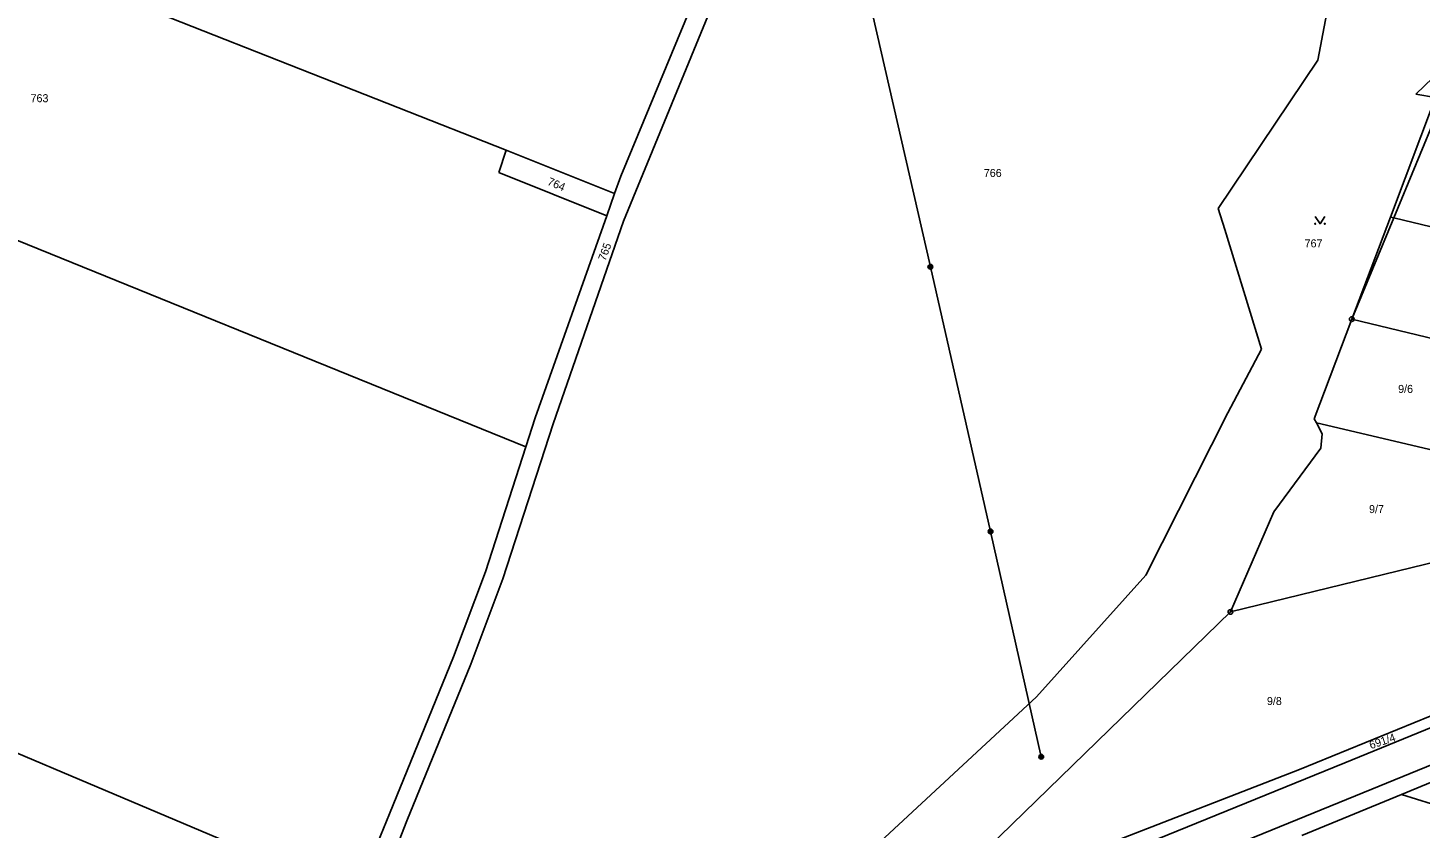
# Model space of a CAD drawing. Extents: x -738131 to -734179, y -1033447 to -1030078.
# Drawn here: x -736626.5 to -736330.8, y -1032337 to -1032166.9 of the extents above; entities that cross this region are included whole.
import ezdxf

# ---------------------------------------------------------------- set-up
doc = ezdxf.new("R2010")
doc.units = 0
for name, color, linetype in [('Vrstva 1', 7, 'Continuous'), ('Vrstva 2', 7, 'Continuous'), ('Vrstva 3', 7, 'Continuous'), ('Vrstva 4', 7, 'Continuous'), ('Vrstva 6', 7, 'Continuous'), ('Vrstva 8', 7, 'Continuous')]:
    doc.layers.add(name, color=color, linetype=linetype)

msp = doc.modelspace()

# ---------------------------------------------------------------- linework, layer by layer
at = {"layer": 'Vrstva 1'}
for points in [[(-736500.59, -1032198.46), (-736474.94, -1032136.53)], [(-736471.25, -1032138.06), (-736500.01, -1032208)], [(-736524.9, -1032192.93), (-736640.1, -1032147.52)], [(-736349.56, -1032158.09), (-736352.54, -1032173.8)], [(-736352.54, -1032173.8), (-736373.67, -1032205.35)], [(-736331.67, -1032181.03), (-736324.54, -1032174.18)], [(-736337.12, -1032207.13), (-736327.53, -1032181.71)], [(-736327.53, -1032181.71), (-736331.67, -1032181.03)], [(-736524.9, -1032192.93), (-736526.51, -1032197.67)], [(-736524.9, -1032192.93), (-736501.9, -1032202.15)], [(-736526.51, -1032197.67), (-736503.58, -1032206.9)], [(-736501.9, -1032202.15), (-736500.59, -1032198.46)], [(-736503.58, -1032206.9), (-736501.9, -1032202.15)], [(-736647.76, -1032204.41), (-736520.74, -1032255.93)], [(-736373.67, -1032205.35), (-736372.27, -1032209.79)], [(-736518.76, -1032249.79), (-736503.58, -1032206.9)], [(-736500.01, -1032208), (-736514.97, -1032251.07)], [(-736345.31, -1032228.83), (-736337.12, -1032207.13)], [(-736336.37, -1032207.29), (-736337.12, -1032207.13)], [(-736296.74, -1032216.86), (-736336.37, -1032207.29)], [(-736372.27, -1032209.79), (-736364.51, -1032235.17)], [(-736353.3, -1032250.02), (-736345.31, -1032228.83)], [(-736345.31, -1032228.83), (-736305.65, -1032238.38)], [(-736364.51, -1032235.17), (-736371.65, -1032248.71)], [(-736520.74, -1032255.93), (-736518.76, -1032249.79)], [(-736371.65, -1032248.71), (-736389.06, -1032283.24)], [(-736525.62, -1032284.03), (-736514.97, -1032251.07)], [(-736352.83, -1032250.89), (-736353.3, -1032250.02)], [(-736314.55, -1032259.88), (-736352.83, -1032250.89)], [(-736351.58, -1032253.21), (-736352.83, -1032250.89)], [(-736351.91, -1032256.24), (-736351.58, -1032253.21)], [(-736529.33, -1032282.53), (-736520.74, -1032255.93)], [(-736361.89, -1032269.76), (-736351.91, -1032256.24)], [(-736371.09, -1032291.04), (-736361.89, -1032269.76)], [(-736326.68, -1032280.18), (-736371.09, -1032291.04)], [(-736536.12, -1032300.55), (-736529.33, -1032282.53)], [(-736532.44, -1032302.11), (-736525.62, -1032284.03)], [(-736412.26, -1032309.06), (-736389.06, -1032283.24)], [(-736438.11, -1032356.21), (-736371.09, -1032291.04)], [(-736687.94, -1032296.02), (-736556.66, -1032351.59)], [(-736346.81, -1032323.08), (-736277.07, -1032294.54)], [(-736549.74, -1032333.93), (-736536.12, -1032300.55)], [(-736546.04, -1032335.44), (-736532.44, -1032302.11)], [(-736274.85, -1032301.61), (-736344.52, -1032330.1)], [(-736465.97, -1032358.86), (-736412.26, -1032309.06)], [(-736325.19, -1032311.77), (-736356.43, -1032324.48)], [(-736346.81, -1032323.08), (-736443.2, -1032362.35)], [(-736356.43, -1032324.48), (-736438.11, -1032356.21)], [(-736324.11, -1032325.43), (-736334.74, -1032329.85)], [(-736440.69, -1032369.33), (-736344.52, -1032330.1)], [(-736334.74, -1032329.85), (-736355.89, -1032338.5)], [(-736325.2, -1032332.8), (-736334.74, -1032329.85)], [(-736553.55, -1032343.26), (-736549.74, -1032333.93)], [(-736553.28, -1032353.98), (-736546.04, -1032335.44)]]:
    msp.add_lwpolyline(points, dxfattribs=at)
at = {"layer": 'Vrstva 3'}
msp.add_lwpolyline([(-736353.06, -1032207.05), (-736352.06, -1032208.55), (-736351.06, -1032207.05)], dxfattribs=at)
for centre in [(-736353.06, -1032208.55), (-736351.06, -1032208.55)]:
    msp.add_circle(centre, 0.1, dxfattribs=at)
at = {"layer": 'Vrstva 4'}
for points in [[(-736336.37, -1032207.29), (-736326.88, -1032184.34)], [(-736345.31, -1032228.83), (-736336.37, -1032207.29)]]:
    msp.add_lwpolyline(points, dxfattribs=at)
at = {"layer": 'Vrstva 6'}
for points in [[(-736434.83, -1032217.69), (-736448, -1032160.21)], [(-736422.05, -1032273.93), (-736434.83, -1032217.69)], [(-736411.27, -1032321.8), (-736422.05, -1032273.93)]]:
    msp.add_lwpolyline(points, dxfattribs=at)
for centre, radius in [((-736434.83, -1032217.69), 0.5), ((-736434.83, -1032217.69), 0.4), ((-736434.83, -1032217.69), 0.3), ((-736434.83, -1032217.69), 0.2), ((-736434.83, -1032217.69), 0.1), ((-736422.05, -1032273.93), 0.5), ((-736422.05, -1032273.93), 0.4), ((-736422.05, -1032273.93), 0.3), ((-736422.05, -1032273.93), 0.2), ((-736422.05, -1032273.93), 0.1), ((-736411.27, -1032321.8), 0.5), ((-736411.27, -1032321.8), 0.4), ((-736411.27, -1032321.8), 0.3), ((-736411.27, -1032321.8), 0.2), ((-736411.27, -1032321.8), 0.1)]:
    msp.add_circle(centre, radius, dxfattribs=at)
at = {"layer": 'Vrstva 8'}
for centre, radius in [((-736345.31, -1032228.83), 0.5), ((-736345.31, -1032228.83), 0.0303), ((-736371.09, -1032291.04), 0.5), ((-736371.09, -1032291.04), 0.5), ((-736371.09, -1032291.04), 0.0303), ((-736371.09, -1032291.04), 0.0303)]:
    msp.add_circle(centre, radius, dxfattribs=at)

# ---------------------------------------------------------------- texts
at = {"layer": 'Vrstva 2'}
for s, p in [('763', (-736625.96, -1032182.74)), ('766', (-736423.47, -1032198.62)), ('767', (-736355.33, -1032213.57)), ('9/6', (-736335.46, -1032244.5)), ('9/7', (-736341.64, -1032270.03)), ('9/8', (-736363.33, -1032310.81))]:
    msp.add_text(s, height=1.7, dxfattribs=at).set_placement(p)
for s, rotation, p in [('764', 337.0817, (-736516.32, -1032200.21)), ('765', 69.6717, (-736503.86, -1032216.58)), ('691/4', 18.435, (-736341.25, -1032320.2))]:
    msp.add_text(s, height=1.7, rotation=rotation, dxfattribs=at).set_placement(p)

doc.saveas('drawing.dxf')
